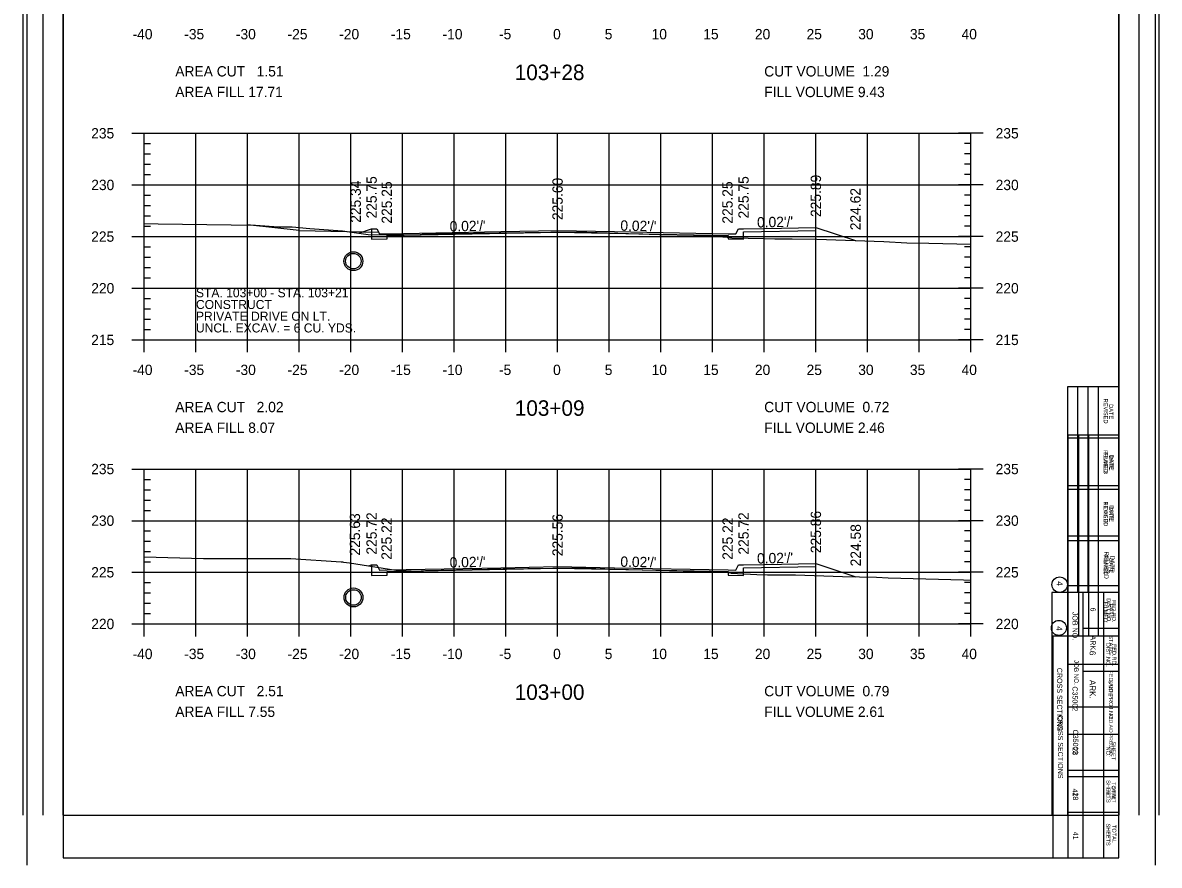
# Model space of a CAD drawing. Extents: x 1367903 to 1373764, y 376865 to 382130.
# Drawn here: x 1370451.5 to 1370671.5, y 377279.1 to 377442.3 of the extents above; entities that cross this region are included whole.
import ezdxf

# ---------------------------------------------------------------- set-up
doc = ezdxf.new("R2010")
doc.units = 0
for name, color, linetype in [('R_Axis', 7, 'Continuous'), ('R_Axis Annot', 7, 'Continuous'), ('R_Border', 7, 'Continuous'), ('R_Border Notes', 7, 'Continuous'), ('R_Border PE', 7, 'Continuous'), ('R_Draft', 7, 'Continuous'), ('R_Drive', 7, 'Continuous'), ('R_Exist Surface', 7, 'Continuous'), ('R_Fin Surface', 7, 'Continuous'), ('R_Fin Surface Annot', 7, 'Continuous'), ('R_Grid', 7, 'Continuous'), ('R_Water', 7, 'Continuous')]:
    doc.layers.add(name, color=color, linetype=linetype)

msp = doc.modelspace()

# ---------------------------------------------------------------- linework, layer by layer
for points in [[(1370518.98, 377402.35), (1370518.98, 377401.68), (1370518.98, 377401.68), (1370518.98, 377400.32), (1370521.98, 377400.38), (1370521.98, 377401.04), (1370554.98, 377401.7), (1370587.98, 377401.04), (1370587.98, 377400.38), (1370590.98, 377400.32), (1370590.98, 377401.76), (1370604.98, 377402.04), (1370604.98, 377402.63)], [(1370518.98, 377337.27), (1370518.98, 377336.61), (1370518.98, 377336.61), (1370518.98, 377335.24), (1370521.98, 377335.3), (1370521.98, 377335.97), (1370554.98, 377336.63), (1370587.98, 377335.97), (1370587.98, 377335.3), (1370590.98, 377335.24), (1370590.98, 377336.69), (1370604.98, 377336.97), (1370604.98, 377337.55)]]:
    msp.add_lwpolyline(points)
at = {"layer": 'R_Axis'}
for p, q in [((1370472.58, 377420.84), (1370477.38, 377420.84)), ((1370474.98, 377380.84), (1370474.98, 377420.84)), ((1370637.38, 377420.84), (1370632.58, 377420.84)), ((1370634.98, 377380.84), (1370634.98, 377420.84)), ((1370474.98, 377418.84), (1370476.18, 377418.84)), ((1370634.98, 377418.84), (1370633.78, 377418.84)), ((1370474.98, 377416.84), (1370476.18, 377416.84)), ((1370634.98, 377416.84), (1370633.78, 377416.84)), ((1370474.98, 377414.84), (1370476.18, 377414.84)), ((1370474.98, 377412.84), (1370476.18, 377412.84)), ((1370634.98, 377414.84), (1370633.78, 377414.84)), ((1370634.98, 377412.84), (1370633.78, 377412.84)), ((1370472.58, 377410.84), (1370477.38, 377410.84)), ((1370637.38, 377410.84), (1370632.58, 377410.84)), ((1370474.98, 377408.84), (1370476.18, 377408.84)), ((1370634.98, 377408.84), (1370633.78, 377408.84)), ((1370474.98, 377406.84), (1370476.18, 377406.84)), ((1370634.98, 377406.84), (1370633.78, 377406.84)), ((1370474.98, 377404.84), (1370476.18, 377404.84)), ((1370634.98, 377404.84), (1370633.78, 377404.84)), ((1370474.98, 377402.84), (1370476.18, 377402.84)), ((1370634.98, 377402.84), (1370633.78, 377402.84)), ((1370472.58, 377400.84), (1370477.38, 377400.84)), ((1370637.38, 377400.84), (1370632.58, 377400.84)), ((1370474.98, 377398.84), (1370476.18, 377398.84)), ((1370634.98, 377398.84), (1370633.78, 377398.84)), ((1370474.98, 377396.84), (1370476.18, 377396.84)), ((1370634.98, 377396.84), (1370633.78, 377396.84)), ((1370474.98, 377394.84), (1370476.18, 377394.84)), ((1370634.98, 377394.84), (1370633.78, 377394.84)), ((1370472.58, 377390.84), (1370477.38, 377390.84)), ((1370474.98, 377392.84), (1370476.18, 377392.84)), ((1370637.38, 377390.84), (1370632.58, 377390.84)), ((1370634.98, 377392.84), (1370633.78, 377392.84)), ((1370474.98, 377388.84), (1370476.18, 377388.84)), ((1370634.98, 377388.84), (1370633.78, 377388.84)), ((1370474.98, 377386.84), (1370476.18, 377386.84)), ((1370634.98, 377386.84), (1370633.78, 377386.84)), ((1370474.98, 377384.84), (1370476.18, 377384.84)), ((1370634.98, 377384.84), (1370633.78, 377384.84)), ((1370474.98, 377378.44), (1370474.98, 377383.24)), ((1370474.98, 377382.84), (1370476.18, 377382.84)), ((1370484.98, 377378.44), (1370484.98, 377383.24)), ((1370494.98, 377378.44), (1370494.98, 377383.24)), ((1370504.98, 377378.44), (1370504.98, 377383.24)), ((1370514.98, 377378.44), (1370514.98, 377383.24)), ((1370524.98, 377378.44), (1370524.98, 377383.24)), ((1370534.98, 377378.44), (1370534.98, 377383.24)), ((1370544.98, 377378.44), (1370544.98, 377383.24)), ((1370554.98, 377378.44), (1370554.98, 377383.24)), ((1370564.98, 377378.44), (1370564.98, 377383.24)), ((1370574.98, 377378.44), (1370574.98, 377383.24)), ((1370584.98, 377378.44), (1370584.98, 377383.24)), ((1370594.98, 377378.44), (1370594.98, 377383.24)), ((1370604.98, 377378.44), (1370604.98, 377383.24)), ((1370614.98, 377378.44), (1370614.98, 377383.24)), ((1370624.98, 377378.44), (1370624.98, 377383.24)), ((1370634.98, 377382.84), (1370633.78, 377382.84)), ((1370634.98, 377378.44), (1370634.98, 377383.24)), ((1370472.58, 377380.84), (1370477.38, 377380.84)), ((1370474.98, 377380.84), (1370634.98, 377380.84)), ((1370637.38, 377380.84), (1370632.58, 377380.84)), ((1370472.58, 377355.84), (1370477.38, 377355.84)), ((1370474.98, 377325.84), (1370474.98, 377355.84)), ((1370637.38, 377355.84), (1370632.58, 377355.84)), ((1370634.98, 377325.84), (1370634.98, 377355.84)), ((1370474.98, 377353.84), (1370476.18, 377353.84)), ((1370634.98, 377353.84), (1370633.78, 377353.84)), ((1370474.98, 377351.84), (1370476.18, 377351.84)), ((1370634.98, 377351.84), (1370633.78, 377351.84)), ((1370474.98, 377349.84), (1370476.18, 377349.84)), ((1370634.98, 377349.84), (1370633.78, 377349.84)), ((1370474.98, 377347.84), (1370476.18, 377347.84)), ((1370634.98, 377347.84), (1370633.78, 377347.84)), ((1370472.58, 377345.84), (1370477.38, 377345.84)), ((1370637.38, 377345.84), (1370632.58, 377345.84)), ((1370474.98, 377343.84), (1370476.18, 377343.84)), ((1370634.98, 377343.84), (1370633.78, 377343.84)), ((1370474.98, 377341.84), (1370476.18, 377341.84)), ((1370634.98, 377341.84), (1370633.78, 377341.84)), ((1370474.98, 377339.84), (1370476.18, 377339.84)), ((1370634.98, 377339.84), (1370633.78, 377339.84)), ((1370472.58, 377335.84), (1370477.38, 377335.84)), ((1370474.98, 377337.84), (1370476.18, 377337.84)), ((1370637.38, 377335.84), (1370632.58, 377335.84)), ((1370634.98, 377337.84), (1370633.78, 377337.84)), ((1370474.98, 377333.84), (1370476.18, 377333.84)), ((1370634.98, 377333.84), (1370633.78, 377333.84)), ((1370474.98, 377331.84), (1370476.18, 377331.84)), ((1370634.98, 377331.84), (1370633.78, 377331.84)), ((1370474.98, 377329.84), (1370476.18, 377329.84)), ((1370634.98, 377329.84), (1370633.78, 377329.84)), ((1370474.98, 377323.44), (1370474.98, 377328.24)), ((1370474.98, 377327.84), (1370476.18, 377327.84)), ((1370484.98, 377323.44), (1370484.98, 377328.24)), ((1370494.98, 377323.44), (1370494.98, 377328.24)), ((1370504.98, 377323.44), (1370504.98, 377328.24)), ((1370514.98, 377323.44), (1370514.98, 377328.24)), ((1370524.98, 377323.44), (1370524.98, 377328.24)), ((1370534.98, 377323.44), (1370534.98, 377328.24)), ((1370544.98, 377323.44), (1370544.98, 377328.24)), ((1370554.98, 377323.44), (1370554.98, 377328.24)), ((1370564.98, 377323.44), (1370564.98, 377328.24)), ((1370574.98, 377323.44), (1370574.98, 377328.24)), ((1370584.98, 377323.44), (1370584.98, 377328.24)), ((1370594.98, 377323.44), (1370594.98, 377328.24)), ((1370604.98, 377323.44), (1370604.98, 377328.24)), ((1370614.98, 377323.44), (1370614.98, 377328.24)), ((1370624.98, 377323.44), (1370624.98, 377328.24)), ((1370634.98, 377327.84), (1370633.78, 377327.84)), ((1370634.98, 377323.44), (1370634.98, 377328.24)), ((1370472.58, 377325.84), (1370477.38, 377325.84)), ((1370474.98, 377325.84), (1370634.98, 377325.84)), ((1370637.38, 377325.84), (1370632.58, 377325.84))]:
    msp.add_line(p, q, dxfattribs=at)
at = {"layer": 'R_Border'}
for p, q in [((1370452.26, 377620.35), (1370452.26, 377279.12)), ((1370670.65, 377620.35), (1370670.65, 377279.12)), ((1370459.29, 377611.47), (1370459.29, 377280.59)), ((1370663.61, 377280.59), (1370663.61, 377611.47)), ((1370653.8, 377280.59), (1370653.8, 377362.43)), ((1370653.8, 377362.43), (1370663.61, 377362.43)), ((1370653.8, 377362.43), (1370655.83, 377362.43)), ((1370655.83, 377362.43), (1370655.83, 377323.46)), ((1370657.78, 377362.43), (1370657.78, 377323.46)), ((1370659.63, 377362.43), (1370659.63, 377323.46)), ((1370653.8, 377352.62), (1370663.42, 377352.62)), ((1370653.8, 377342.9), (1370663.42, 377342.9)), ((1370653.8, 377333.27), (1370663.42, 377333.27)), ((1370663.61, 377323.46), (1370650.88, 377323.46)), ((1370650.88, 377323.46), (1370650.88, 377280.59)), ((1370656.71, 377280.59), (1370656.71, 377323.46)), ((1370660.69, 377280.59), (1370660.69, 377323.46)), ((1370663.61, 377316.65), (1370656.71, 377316.65)), ((1370663.61, 377309.75), (1370653.8, 377309.75)), ((1370663.61, 377296.24), (1370653.8, 377296.24)), ((1370663.61, 377289.33), (1370653.8, 377289.33)), ((1370459.29, 377280.59), (1370663.61, 377280.59))]:
    msp.add_line(p, q, dxfattribs=at)
msp.add_circle((1370652.02, 377325.07), 1.46, dxfattribs=at)
at = {"layer": 'R_Border PE'}
for p, q in [((1370451.45, 377610.76), (1370451.45, 377288.8)), ((1370455.37, 377610.76), (1370455.37, 377288.8)), ((1370667.54, 377288.8), (1370667.54, 377610.76)), ((1370671.45, 377288.8), (1370671.45, 377610.76)), ((1370459.29, 377288.8), (1370459.29, 377603.25)), ((1370663.61, 377603.25), (1370663.61, 377288.8)), ((1370653.66, 377371.74), (1370653.66, 377288.8)), ((1370663.61, 377371.74), (1370653.66, 377371.74)), ((1370655.65, 377371.74), (1370655.65, 377331.96)), ((1370657.64, 377371.74), (1370657.64, 377331.96)), ((1370659.63, 377371.74), (1370659.63, 377331.96)), ((1370663.61, 377361.8), (1370653.66, 377361.8)), ((1370663.61, 377351.85), (1370653.66, 377351.85)), ((1370663.61, 377341.91), (1370653.66, 377341.91)), ((1370663.61, 377331.96), (1370650.68, 377331.96)), ((1370650.68, 377331.96), (1370650.68, 377288.8)), ((1370656.65, 377331.96), (1370656.65, 377288.8)), ((1370660.63, 377331.96), (1370660.63, 377288.8)), ((1370656.71, 377325), (1370663.61, 377325)), ((1370653.8, 377318.04), (1370663.61, 377318.04)), ((1370653.8, 377304.51), (1370663.61, 377304.51)), ((1370653.8, 377297.55), (1370663.61, 377297.55)), ((1370459.29, 377288.8), (1370663.61, 377288.8)), ((1370660.72, 377288.8), (1370660.72, 377288.8))]:
    msp.add_line(p, q, dxfattribs=at)
msp.add_circle((1370652.17, 377333.45), 1.49, dxfattribs=at)
at = {"layer": 'R_Drive'}
for q in [(1370494.98, 377403.09), (1370520.31, 377401.69)]:
    msp.add_line((1370504.98, 377402), q, dxfattribs=at)
at = {"layer": 'R_Exist Surface'}
for points in [[(1370474.98, 377403.38), (1370477.68, 377403.3), (1370496.48, 377403.08), (1370500.99, 377402.75), (1370503.62, 377402.7), (1370507.03, 377402.4), (1370513.34, 377401.94), (1370518.34, 377401.27), (1370528.02, 377401.21), (1370529.56, 377401.43), (1370533.73, 377401.46), (1370558.66, 377401.75), (1370574.7, 377401.27), (1370574.99, 377401.26), (1370581.32, 377401.11), (1370586.94, 377400.82), (1370587.81, 377400.76), (1370588.27, 377400.64), (1370588.7, 377400.57), (1370595.01, 377400.45), (1370597.04, 377400.4), (1370600.36, 377400.43), (1370605.17, 377400.33), (1370618.12, 377399.88), (1370622.58, 377399.66), (1370626.82, 377399.59), (1370634.98, 377399.36)], [(1370474.98, 377338.82), (1370486.43, 377338.5), (1370500.59, 377338.51), (1370503.37, 377338.49), (1370513.09, 377337.89), (1370513.36, 377337.86), (1370513.56, 377337.83), (1370514.72, 377337.67), (1370523.66, 377336.28), (1370525.58, 377336.11), (1370526.62, 377336.1), (1370528.16, 377336.01), (1370529.44, 377336.22), (1370544.47, 377336.51), (1370558.82, 377336.68), (1370565.96, 377336.47), (1370566.09, 377336.47), (1370584.61, 377336.02), (1370585.47, 377335.98), (1370588.08, 377335.81), (1370588.23, 377335.78), (1370588.6, 377335.68), (1370593.53, 377335.41), (1370595.62, 377335.36), (1370596.74, 377335.38), (1370601.05, 377335.33), (1370610.12, 377335.03), (1370616.72, 377334.91), (1370619, 377334.79), (1370633.55, 377334.4), (1370634.98, 377334.34)]]:
    msp.add_lwpolyline(points, dxfattribs=at)
at = {"layer": 'R_Fin Surface'}
for points in [[(1370516.49, 377401.51), (1370518.98, 377402.35), (1370519.98, 377402.35), (1370520.48, 377401.35), (1370521.98, 377401.38), (1370543.98, 377401.82), (1370554.98, 377402.04), (1370565.98, 377401.82), (1370587.98, 377401.38), (1370589.48, 377401.35), (1370589.98, 377402.35), (1370590.98, 377402.35), (1370594.98, 377402.43), (1370604.98, 377402.63), (1370612.64, 377400.07)], [(1370518.44, 377337.09), (1370518.98, 377337.27), (1370519.98, 377337.27), (1370520.48, 377336.27), (1370521.98, 377336.3), (1370543.98, 377336.74), (1370554.98, 377336.96), (1370565.98, 377336.74), (1370587.98, 377336.3), (1370589.48, 377336.27), (1370589.98, 377337.27), (1370590.98, 377337.27), (1370594.98, 377337.35), (1370604.98, 377337.55), (1370612.69, 377334.99)]]:
    msp.add_lwpolyline(points, dxfattribs=at)
at = {"layer": 'R_Grid'}
for p, q in [((1370474.98, 377420.84), (1370634.98, 377420.84)), ((1370474.98, 377380.84), (1370474.98, 377420.84)), ((1370484.98, 377380.84), (1370484.98, 377420.84)), ((1370494.98, 377380.84), (1370494.98, 377420.84)), ((1370504.98, 377380.84), (1370504.98, 377420.84)), ((1370514.98, 377380.84), (1370514.98, 377420.84)), ((1370524.98, 377380.84), (1370524.98, 377420.84)), ((1370534.98, 377380.84), (1370534.98, 377420.84)), ((1370544.98, 377380.84), (1370544.98, 377420.84)), ((1370554.98, 377380.84), (1370554.98, 377420.84)), ((1370564.98, 377380.84), (1370564.98, 377420.84)), ((1370574.98, 377380.84), (1370574.98, 377420.84)), ((1370584.98, 377380.84), (1370584.98, 377420.84)), ((1370594.98, 377380.84), (1370594.98, 377420.84)), ((1370604.98, 377380.84), (1370604.98, 377420.84)), ((1370614.98, 377380.84), (1370614.98, 377420.84)), ((1370624.98, 377380.84), (1370624.98, 377420.84)), ((1370634.98, 377380.84), (1370634.98, 377420.84)), ((1370474.98, 377410.84), (1370634.98, 377410.84)), ((1370474.98, 377400.84), (1370634.98, 377400.84)), ((1370474.98, 377390.84), (1370634.98, 377390.84)), ((1370474.98, 377380.84), (1370634.98, 377380.84)), ((1370474.98, 377355.84), (1370634.98, 377355.84)), ((1370474.98, 377325.84), (1370474.98, 377355.84)), ((1370484.98, 377325.84), (1370484.98, 377355.84)), ((1370494.98, 377325.84), (1370494.98, 377355.84)), ((1370504.98, 377325.84), (1370504.98, 377355.84)), ((1370514.98, 377325.84), (1370514.98, 377355.84)), ((1370524.98, 377325.84), (1370524.98, 377355.84)), ((1370534.98, 377325.84), (1370534.98, 377355.84)), ((1370544.98, 377325.84), (1370544.98, 377355.84)), ((1370554.98, 377325.84), (1370554.98, 377355.84)), ((1370564.98, 377325.84), (1370564.98, 377355.84)), ((1370574.98, 377325.84), (1370574.98, 377355.84)), ((1370584.98, 377325.84), (1370584.98, 377355.84)), ((1370594.98, 377325.84), (1370594.98, 377355.84)), ((1370604.98, 377325.84), (1370604.98, 377355.84)), ((1370614.98, 377325.84), (1370614.98, 377355.84)), ((1370624.98, 377325.84), (1370624.98, 377355.84)), ((1370634.98, 377325.84), (1370634.98, 377355.84)), ((1370474.98, 377345.84), (1370634.98, 377345.84)), ((1370474.98, 377335.84), (1370634.98, 377335.84)), ((1370474.98, 377325.84), (1370634.98, 377325.84))]:
    msp.add_line(p, q, dxfattribs=at)
at = {"layer": 'R_Water'}
for p, q in [((1370515.46, 377397.94), (1370515.46, 377397.89)), ((1370515.46, 377397.6), (1370515.46, 377397.56)), ((1370515.46, 377394.6), (1370515.46, 377394.56)), ((1370515.46, 377394.27), (1370515.46, 377394.22)), ((1370515.46, 377332.84), (1370515.47, 377332.79)), ((1370515.46, 377332.5), (1370515.47, 377332.45)), ((1370515.46, 377329.5), (1370515.47, 377329.45)), ((1370515.46, 377329.17), (1370515.47, 377329.12))]:
    msp.add_line(p, q, dxfattribs=at)
for centre, radius in [((1370515.46, 377396.08), 1.83), ((1370515.46, 377396.08), 1.5), ((1370515.47, 377330.98), 1.83), ((1370515.47, 377330.98), 1.5)]:
    msp.add_circle(centre, radius, dxfattribs=at)

# ---------------------------------------------------------------- texts
at = {"layer": 'R_Axis Annot'}
for s, height, p in [('-40', 2, (1370472.71, 377439.04)), ('-35', 2, (1370482.71, 377439.04)), ('-30', 2, (1370492.71, 377439.04)), ('-25', 2, (1370502.71, 377439.04)), ('-20', 2, (1370512.71, 377439.04)), ('-15', 2, (1370522.71, 377439.04)), ('-10', 2, (1370532.71, 377439.04)), ('-5', 2, (1370543.64, 377439.04)), ('0', 2, (1370554.11, 377439.04)), ('5', 2, (1370564.11, 377439.04)), ('10', 2, (1370573.18, 377439.04)), ('15', 2, (1370583.18, 377439.04)), ('20', 2, (1370593.18, 377439.04)), ('25', 2, (1370603.18, 377439.04)), ('30', 2, (1370613.18, 377439.04)), ('35', 2, (1370623.18, 377439.04)), ('40', 2, (1370633.18, 377439.04)), ('AREA CUT   1.51', 2, (1370480.98, 377431.84)), ('103+28', 3, (1370546.69, 377431.14)), ('CUT VOLUME  1.29', 2, (1370594.98, 377431.84)), ('AREA FILL 17.71', 2, (1370480.98, 377427.84)), ('FILL VOLUME 9.43', 2, (1370594.98, 377427.84)), ('235', 2, (1370464.7, 377419.84)), ('235', 2, (1370639.78, 377419.84)), ('230', 2, (1370464.71, 377409.84)), ('230', 2, (1370639.78, 377409.84)), ('225', 2, (1370464.7, 377399.84)), ('225', 2, (1370639.78, 377399.84)), ('220', 2, (1370464.71, 377389.84)), ('220', 2, (1370639.78, 377389.84)), ('215', 2, (1370464.7, 377379.84)), ('215', 2, (1370639.78, 377379.84)), ('-40', 2, (1370472.71, 377374.04)), ('-35', 2, (1370482.71, 377374.04)), ('-30', 2, (1370492.71, 377374.04)), ('-25', 2, (1370502.71, 377374.04)), ('-20', 2, (1370512.71, 377374.04)), ('-15', 2, (1370522.71, 377374.04)), ('-10', 2, (1370532.71, 377374.04)), ('-5', 2, (1370543.64, 377374.04)), ('0', 2, (1370554.11, 377374.04)), ('5', 2, (1370564.11, 377374.04)), ('10', 2, (1370573.18, 377374.04)), ('15', 2, (1370583.18, 377374.04)), ('20', 2, (1370593.18, 377374.04)), ('25', 2, (1370603.18, 377374.04)), ('30', 2, (1370613.18, 377374.04)), ('35', 2, (1370623.18, 377374.04)), ('40', 2, (1370633.18, 377374.04)), ('AREA CUT   2.02', 2, (1370480.98, 377366.84)), ('103+09', 3, (1370546.7, 377366.14)), ('CUT VOLUME  0.72', 2, (1370594.98, 377366.84)), ('AREA FILL 8.07', 2, (1370480.98, 377362.84)), ('FILL VOLUME 2.46', 2, (1370594.98, 377362.84)), ('235', 2, (1370464.7, 377354.84)), ('235', 2, (1370639.78, 377354.84)), ('230', 2, (1370464.71, 377344.84)), ('230', 2, (1370639.78, 377344.84)), ('225', 2, (1370464.7, 377334.84)), ('225', 2, (1370639.78, 377334.84)), ('220', 2, (1370464.71, 377324.84)), ('220', 2, (1370639.78, 377324.84)), ('-40', 2, (1370472.71, 377319.04)), ('-35', 2, (1370482.71, 377319.04)), ('-30', 2, (1370492.71, 377319.04)), ('-25', 2, (1370502.71, 377319.04)), ('-20', 2, (1370512.71, 377319.04)), ('-15', 2, (1370522.71, 377319.04)), ('-10', 2, (1370532.71, 377319.04)), ('-5', 2, (1370543.64, 377319.04)), ('0', 2, (1370554.11, 377319.04)), ('5', 2, (1370564.11, 377319.04)), ('10', 2, (1370573.18, 377319.04)), ('15', 2, (1370583.18, 377319.04)), ('20', 2, (1370593.18, 377319.04)), ('25', 2, (1370603.18, 377319.04)), ('30', 2, (1370613.18, 377319.04)), ('35', 2, (1370623.18, 377319.04)), ('40', 2, (1370633.18, 377319.04)), ('AREA CUT   2.51', 2, (1370480.98, 377311.84)), ('103+00', 3, (1370546.69, 377311.14)), ('CUT VOLUME  0.79', 2, (1370594.98, 377311.84)), ('AREA FILL 7.55', 2, (1370480.98, 377307.84)), ('FILL VOLUME 2.61', 2, (1370594.98, 377307.84))]:
    msp.add_text(s, height=height, dxfattribs=at).set_placement(p)
at = {"layer": 'R_Border'}
for s, height, p in [('REVISED', 0.778, (1370660.69, 377359.51)), ('DATE', 0.778, (1370661.86, 377358.64)), ('FILMED', 0.778, (1370660.69, 377349.41)), ('DATE', 0.778, (1370661.86, 377348.82)), ('REVISED', 0.875, (1370660.8, 377339.88)), ('DATE', 0.875, (1370661.96, 377339.1)), ('FILMED', 0.778, (1370660.69, 377330.16)), ('DATE', 0.778, (1370661.86, 377329.77)), ('4', 1.17, (1370651.51, 377325.4)), ('6', 1.17, (1370657.97, 377320.63)), ('DIST.NO.', 0.778, (1370661.19, 377322.19)), ('FED.RD.', 0.778, (1370662.35, 377321.99)), ('JOB NO.', 0.875, (1370654.96, 377318.88)), ('ARK.', 1.166, (1370657.97, 377315)), ('STATE', 0.681, (1370661.67, 377314.9)), ('FED.AID PROJ.NO.', 0.6805, (1370661.77, 377308.49)), ('SHEET', 0.681, (1370662.35, 377294.39)), ('NO.', 0.681, (1370661.19, 377293.61)), ('SHEETS', 0.778, (1370661.19, 377287.2)), ('TOTAL', 0.778, (1370662.35, 377286.91))]:
    msp.add_text(s, height=height, rotation=270, dxfattribs=at).set_placement(p)
at = {"layer": 'R_Border Notes'}
for s, height, p in [('CROSS SECTIONS', 0.9945, (1370651.84, 377308.2)), ('C35002', 0.995, (1370654.76, 377305.39)), ('28', 0.995, (1370654.76, 377293.23)), ('41', 0.995, (1370654.76, 377285.62))]:
    msp.add_text(s, height=height, rotation=270, dxfattribs=at).set_placement(p)
at = {"layer": 'R_Border PE'}
for s, height, p in [('REVISED', 0.796, (1370660.71, 377369.47)), ('DATE', 0.796, (1370661.74, 377368.41)), ('FILMED', 0.796, (1370660.71, 377359.12)), ('DATE', 0.796, (1370661.74, 377358.47)), ('REVISED', 0.796, (1370660.71, 377349.57)), ('DATE', 0.796, (1370661.74, 377348.52)), ('FILMED', 0.796, (1370660.71, 377339.23)), ('DATE', 0.796, (1370661.74, 377338.58)), ('4', 1.19, (1370651.58, 377334.12)), ('DIST.NO.', 0.796, (1370661.28, 377330.83)), ('FED.RD.', 0.796, (1370662.31, 377330.52)), ('JOB NO.', 0.995, (1370654.66, 377328.19)), ('6', 0.995, (1370658.14, 377329.02)), ('ARK.', 0.995, (1370658.14, 377323.6)), ('STATE', 0.796, (1370661.72, 377323.66)), ('CROSS SECTIONS', 0.9945, (1370651.68, 377317.35)), ('FED.AID PROJ.NO.', 0.7956, (1370661.72, 377316.88)), ('C35002', 0.995, (1370654.66, 377313.75)), ('SHEET', 0.796, (1370662.24, 377303.09)), ('28', 0.995, (1370654.66, 377301.96)), ('NO.', 0.796, (1370661.2, 377302.11)), ('SHEETS', 0.796, (1370661.2, 377295.62)), ('TOTAL', 0.796, (1370662.24, 377295.23)), ('41', 0.995, (1370654.66, 377293.96))]:
    msp.add_text(s, height=height, rotation=270, dxfattribs=at).set_placement(p)
at = {"layer": 'R_Draft'}
for s, p in [('STA. 103+00 - STA. 103+21', (1370484.98, 377389.09)), ('CONSTRUCT', (1370484.98, 377386.82)), ('PRIVATE DRIVE ON LT.', (1370484.98, 377384.55)), ('UNCL. EXCAV. = 6 CU. YDS.', (1370484.98, 377382.28))]:
    msp.add_text(s, height=1.75, dxfattribs=at).set_placement(p)
at = {"layer": 'R_Fin Surface Annot'}
for s, rotation, p in [('225.34', 90, (1370516.9, 377403.51)), ('225.75', 90, (1370519.98, 377404.35)), ('225.25', 90, (1370522.92, 377403.35)), ('225.60', 90, (1370555.98, 377404.04)), ('225.25', 90, (1370588.87, 377403.35)), ('225.75', 90, (1370591.98, 377404.35)), ('225.89', 90, (1370605.98, 377404.63)), ('224.62', 90, (1370613.64, 377402.07)), ("0.02'/'", 1.1458, (1370534.11, 377401.82)), ("0.02'/'", 358.8542, (1370567.12, 377401.99)), ("0.02'/'", 1.1458, (1370593.61, 377402.6)), ('225.63', 90, (1370516.75, 377339.09)), ('225.72', 90, (1370519.98, 377339.27)), ('225.56', 90, (1370555.98, 377338.96)), ('225.72', 90, (1370591.98, 377339.27)), ('225.86', 90, (1370605.98, 377339.55)), ('225.22', 90, (1370522.88, 377338.27)), ('225.22', 90, (1370588.9, 377338.27)), ('224.58', 90, (1370613.69, 377336.99)), ("0.02'/'", 1.1458, (1370534.11, 377336.75)), ("0.02'/'", 358.8542, (1370567.12, 377336.92)), ("0.02'/'", 1.1458, (1370593.61, 377337.53))]:
    msp.add_text(s, height=2, rotation=rotation, dxfattribs=at).set_placement(p)

doc.saveas('drawing.dxf')
